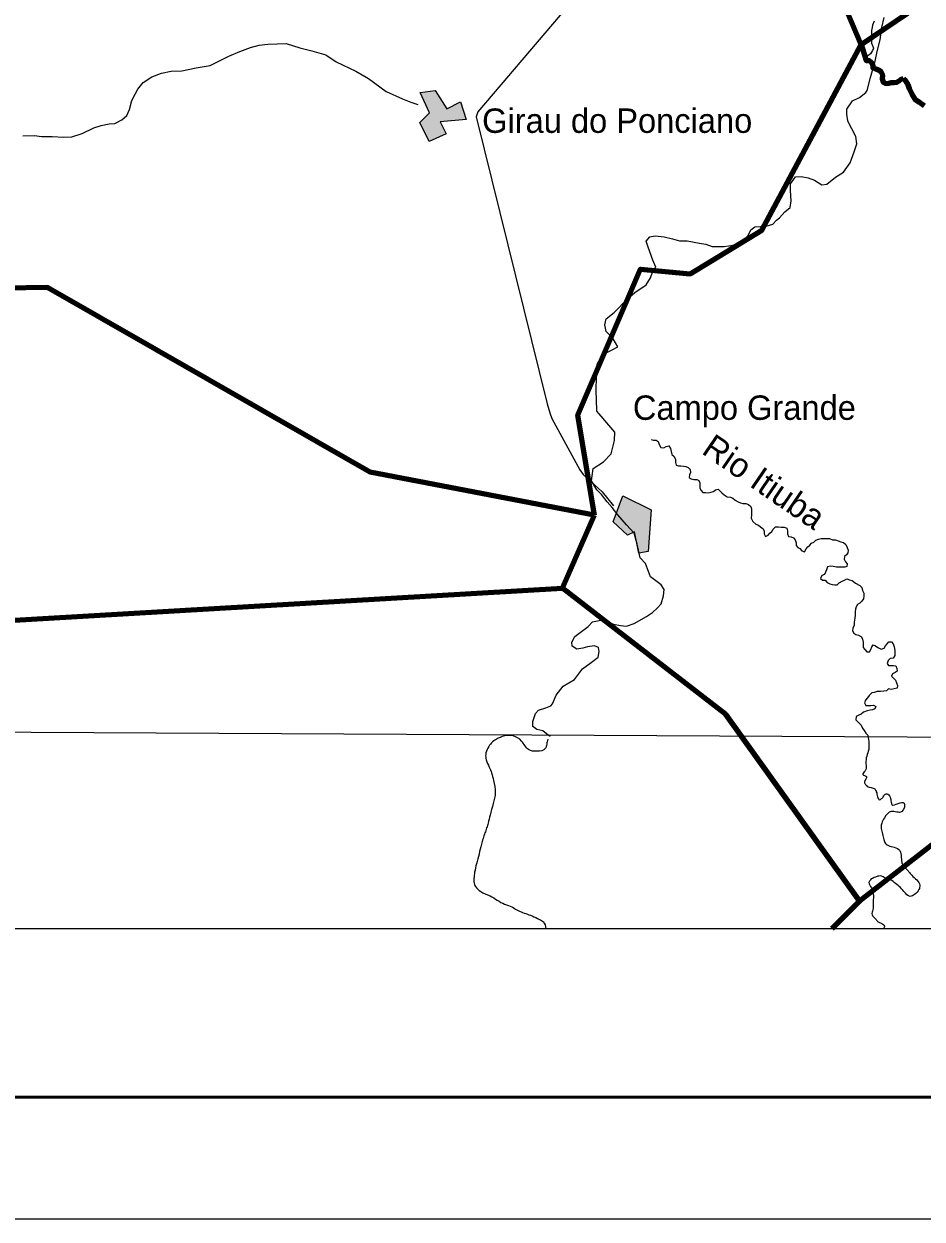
# Model space of a CAD drawing. Extents: x 553962 to 842807, y 8883888 to 9032388.
# Drawn here: x 729677 to 748090, y 8883888 to 8908376 of the extents above; entities that cross this region are included whole.
import ezdxf
from ezdxf.enums import TextEntityAlignment as Align

# ---------------------------------------------------------------- set-up
doc = ezdxf.new("R2010")
doc.units = 0
doc.header["$LTSCALE"] = 200
for name, color, linetype, lineweight in [('1', 7, 'Continuous', 13), ('12', 7, 'Continuous', 25), ('14', 7, 'Continuous', 13), ('21', 7, 'Continuous', 25), ('24', 7, 'Continuous', 25), ('3', 7, 'Continuous', 80), ('9', 7, 'Continuous', 90)]:
    doc.layers.add(name, color=color, linetype=linetype, lineweight=lineweight)
doc.layers.add('41', color=7, linetype='Continuous')
doc.layers.add('49', color=7, linetype='Continuous')

msp = doc.modelspace()

# ---------------------------------------------------------------- hatches: boundary and pattern name
at = {"layer": '21'}
for points in [[(737801.5, 8906970.9), (738106.6, 8907012.5), (738347.6, 8906633.5), (738630.7, 8906778.2), (738745.6, 8906416), (738212.5, 8906368.9), (738331.1, 8906121.9), (737984.3, 8905966.4), (737794.3, 8906356.6), (737990.6, 8906555.2)], [(741953.3, 8898708.5), (742539, 8898421), (742473.5, 8897565.2), (742282.6, 8897532.8), (742195.4, 8897971), (742053.9, 8897898.6), (741759, 8898176.9)]]:
    msp.add_hatch(color=256, dxfattribs=at).paths.add_polyline_path(points)

# ---------------------------------------------------------------- linework, layer by layer
at = {"layer": '1'}
msp.add_lwpolyline([(564751.7, 8894587.5), (664411.9, 8894209.9), (791388.5, 8893536.2)], dxfattribs=at)
at = {"layer": '12'}
for points in [[(746519.8, 8913147), (744583.5, 8912890.8), (744456, 8912865.6), (744221.3, 8912764.1), (744164.9, 8912662.3), (738981.9, 8906574.2), (738945.9, 8906472.4), (740401.6, 8900591.2), (740457, 8900407.7), (740497.3, 8900290.4), (741074.2, 8899240), (741140.1, 8899143.1), (741531, 8898790.9), (741761.4, 8898500.5)], [(732698.6, 8907406), (732912.6, 8907415.8), (733208.3, 8907476.3), (733493.7, 8907526.8), (733646.8, 8907597.8), (733881.6, 8907714.5), (734106.1, 8907810.9), (734320.4, 8907892), (734498.8, 8907937.5), (734677.2, 8907962.7), (734865.7, 8907967.4), (735054.3, 8907977.3), (735334.1, 8907885.1), (735578.4, 8907823.5), (735863.4, 8907741.4), (736076.8, 8907598.4), (736483.7, 8907404.1), (736742.9, 8907255.9), (737103.6, 8906990.3), (737439.3, 8906842), (737612.3, 8906775.4), (737750.2, 8906727.3)], [(729657.5, 8906082), (729896.9, 8906091.7), (730039.5, 8906071.1), (730253.5, 8906065.6), (730497.9, 8906055), (730661, 8906064.9), (730870.1, 8906130.7), (731110, 8906247.4), (731263, 8906293), (731426.1, 8906328.3), (731543.3, 8906338.3), (731686.2, 8906409.4), (731788.5, 8906500.9), (731839.8, 8906623.1), (731891.5, 8906806.3), (731958.2, 8906938.7), (732014.6, 8907040.4), (732122.1, 8907172.7), (732300.8, 8907289.5), (732499.7, 8907365.6), (732698.6, 8907406)]]:
    msp.add_lwpolyline(points, dxfattribs=at)
at = {"layer": '14'}
for points in [[(745102.2, 8904352.2), (745168.7, 8904403), (745276.1, 8904525), (745383.4, 8904616.5), (745404.3, 8904754), (745394.9, 8904962.9), (745395.4, 8905100.4), (745492.7, 8905242.9), (745609.9, 8905247.8), (745752.4, 8905222.1), (745884.7, 8905170.9), (746032.1, 8905078.9), (746139.1, 8905094), (746317.9, 8905236.3), (746481.3, 8905337.9), (746614.5, 8905526.1), (746696.8, 8905755.2), (746753.5, 8905918.1), (746733.6, 8906065.9), (746647.6, 8906229), (746602.1, 8906315.7), (746566.7, 8906392.2), (746546.8, 8906524.7), (746547.2, 8906631.7), (746659.9, 8906799.6), (746807.9, 8906865.5), (746935.6, 8906967.2), (746966.4, 8907012.9), (747033.6, 8907277.7), (747121.3, 8907588.3), (747173.2, 8907837.8), (747230, 8908046.6), (747266.6, 8908301.2), (747313.2, 8908504.9)], [(741412.4, 8901164.9), (741428.6, 8901404.3), (741541.4, 8901602.8), (741720, 8901694.2), (741852.7, 8901760.1), (741756.5, 8901923.3), (741614.4, 8902071.3), (741584.3, 8902208.9), (741610.3, 8902336.2), (741778.9, 8902463.3), (742049.9, 8902742.9), (742198.1, 8902875.1), (742433, 8903027.5), (742520.2, 8903170), (742566.4, 8903287.1), (742633.1, 8903393.9), (742572.5, 8903536.7), (742471.5, 8903801.7), (742436.3, 8903924.1), (742508, 8904010.5), (742615, 8904030.7), (742803.5, 8904015.1), (742976.5, 8903974), (743119, 8903933), (743276.9, 8903932.7), (743526.4, 8903881.3), (743658.8, 8903865.8), (743785.9, 8903814.6), (744035.5, 8903814.1), (744208.8, 8903839.3), (744407.8, 8903920.4), (744525.4, 8904042.5), (744576.8, 8904159.5), (744658.5, 8904215.4), (744892.9, 8904230.3), (745030.6, 8904275.9), (745102.2, 8904352.2)], [(740463, 8893777.9), (740392, 8893831.3), (740315.8, 8893892.6), (740193.7, 8893918.3), (740112.4, 8893979.6), (740107.7, 8894081.4), (740164.3, 8894249.4), (740225.7, 8894315.6), (740378.7, 8894361.1), (740480.7, 8894401.7), (740516.6, 8894447.5), (740588.5, 8894620.5), (740731.8, 8894808.8), (740966.7, 8894940.8), (741130.5, 8895164.6), (741309.3, 8895291.6), (741447.2, 8895398.4), (741468, 8895515.5), (741453.1, 8895602.1), (741371.7, 8895632.8), (741234.1, 8895612.7), (741132.1, 8895587.4), (741009.7, 8895567.3), (740918.2, 8895623.5), (740908.4, 8895710.1), (740969.9, 8895827.1), (741245.8, 8896030.4), (741332.7, 8896127), (741501, 8896162.4), (741587.4, 8896116.4), (741658.7, 8896111.1), (741765.6, 8896075.3), (741908.1, 8896049.6), (742030.3, 8896034.1), (742188.4, 8896089.8), (742438.6, 8896232), (742566.2, 8896313.2), (742668.5, 8896409.8), (742740.1, 8896496.3), (742791.7, 8896659.2), (742802.3, 8896786.6), (742741.6, 8896883.4), (742523.1, 8897046.9), (742417.1, 8897322.1), (742310.6, 8897439.5), (742250.5, 8897714.7), (742190.2, 8897938.9), (742027.8, 8898112.4), (741855.3, 8898316.5), (741733.6, 8898464.5), (741637.2, 8898581.8), (741520.6, 8898734.9), (741424.2, 8898831.8), (741312.8, 8899015.4), (741344.3, 8899265), (741558.7, 8899402.1), (741717.3, 8899569.9), (741784.5, 8899839.8), (741790.2, 8900007.9), (741627.9, 8900201.8), (741470.7, 8900385.4), (741425, 8900441.6), (741415.7, 8900681), (741411.2, 8900849.1), (741412.4, 8901164.9)]]:
    msp.add_lwpolyline(points, dxfattribs=at)
msp.add_spline([(740417.8, 8893718), (740395, 8893617.9), (740366.3, 8893527), (740201.3, 8893471.8), (740024.2, 8893508.9), (739877.2, 8893682.8), (739707.5, 8893786.1), (739358.5, 8893717.2), (739264.2, 8893644.1), (739189.2, 8893539.6), (739143.8, 8893408.5), (739155.2, 8893295.7), (739216.5, 8893150.5), (739263.3, 8893031.3), (739303.8, 8892876.6), (739340.8, 8892619.9), (739297.6, 8892401.9), (739233.3, 8892164.3), (739191.8, 8891997.3), (739163, 8891901.3), (739128.9, 8891800.4), (739054.6, 8891568.2), (739006.8, 8891365.7), (738954.1, 8891168.5), (738917.5, 8890996.2), (738902.9, 8890869.1), (738913.8, 8890741), (738932.9, 8890704.5), (739041.4, 8890598.4), (739232.1, 8890509.7), (739532.1, 8890340.4), (739683, 8890283.8), (739782.9, 8890223.9), (739838, 8890196.4), (740094.7, 8890100.1), (740245.1, 8890028.2), (740325, 8889979.3), (740376.2, 8889839.6), (740376.7, 8889836.8)], degree=3, dxfattribs=at)
at = {"layer": '21'}
for points in [[(737801.5, 8906970.9), (738106.6, 8907012.5), (738347.6, 8906633.5), (738630.7, 8906778.2), (738745.6, 8906416), (738212.5, 8906368.9), (738331.1, 8906121.9), (737984.3, 8905966.4), (737794.3, 8906356.6), (737990.6, 8906555.2)], [(741953.3, 8898708.5), (742539, 8898421), (742473.5, 8897565.2), (742282.6, 8897532.8), (742195.4, 8897971), (742053.9, 8897898.6), (741759, 8898176.9)]]:
    msp.add_lwpolyline(points, close=True, dxfattribs=at)
at = {"layer": '24'}
for points in [[(747110.1, 8908431.2), (747073.9, 8908350), (747068.5, 8908299.1), (747052.8, 8908238.1), (747052.4, 8908177), (747051.8, 8908095.5), (747051.4, 8908034.4), (747051, 8907983.5), (747076.1, 8907932.4), (747091, 8907881.4), (747075.4, 8907830.6), (747029.2, 8907764.6), (746947.3, 8907698.9), (746906.4, 8907668.6), (746941.8, 8907627.7), (747002.8, 8907627.3), (747048.3, 8907591.4), (747078.4, 8907530.1), (747083.1, 8907479.1), (747133.8, 8907458.4), (747194.7, 8907432.6), (747245.3, 8907401.8), (747275.4, 8907335.4), (747274.8, 8907248.8), (747294.7, 8907182.5), (747345.4, 8907156.7), (747406.4, 8907161.4), (747457.4, 8907176.4), (747513.3, 8907176), (747569.3, 8907180.8), (747620.4, 8907211), (747661.3, 8907241.3), (747707.2, 8907261.4)], [(747707.2, 8907261.4), (747727.8, 8907234.4), (747794.5, 8907132.9), (747825.5, 8907051.5), (747877, 8906939.6), (747943.7, 8906833), (748030.5, 8906772.3), (748134.8, 8906696)], [(742537.4, 8899861.4), (742586, 8899849), (742636.8, 8899848.6), (742682.4, 8899822.9), (742702.3, 8899761.6), (742732.4, 8899695.2), (742793.4, 8899689.7), (742844.5, 8899719.9), (742900.5, 8899729.8), (742935.7, 8899678.6), (742945.5, 8899617.4), (742960.3, 8899551.1), (743005.8, 8899510.1), (743035.9, 8899453.8), (743035.5, 8899392.7), (743045.2, 8899331.5), (743096, 8899321), (743146.9, 8899320.7), (743197.7, 8899315.3), (743248.5, 8899304.8), (743294.1, 8899284.1), (743334.5, 8899243.1), (743344.3, 8899187), (743323.6, 8899136.2), (743318.2, 8899085.3), (743358.7, 8899054.4), (743409.4, 8899038.8), (743470.5, 8899038.4), (743516.1, 8899017.8), (743536.1, 8898971.8), (743535.8, 8898920.9), (743535.4, 8898864.8), (743560.5, 8898813.8), (743595.8, 8898777.9), (743646.7, 8898772.4), (743707.7, 8898767), (743763.7, 8898781.9), (743814.7, 8898796.8), (743855.6, 8898827.1), (743906.5, 8898842.1), (743947, 8898811.3), (743982.3, 8898770.3), (744032.9, 8898724.1), (744093.6, 8898683), (744159.7, 8898682.6), (744210.5, 8898661.9), (744261, 8898620.8), (744321.8, 8898584.7), (744367.5, 8898564.1), (744418.2, 8898548.5), (744474.2, 8898548.1), (744530, 8898527.4), (744580.6, 8898491.4), (744595.5, 8898440.3), (744595.1, 8898379.2), (744589.6, 8898318.1), (744584, 8898251.9), (744619.1, 8898180.4), (744679.8, 8898129.1), (744735.6, 8898103.3), (744776.1, 8898072.4), (744831.7, 8898031.3), (744851.8, 8897985.3), (744851.4, 8897929.3), (744881.5, 8897873.1), (744932.6, 8897903.3), (744968.4, 8897938.8), (745009.3, 8897974.2), (745040.2, 8898024.9), (745086.3, 8898070.4), (745147.3, 8898070.1), (745203.2, 8898064.6), (745259.2, 8898064.2), (745315, 8898043.5), (745329.9, 8897992.5), (745329.5, 8897931.3), (745354.5, 8897870.1), (745405.3, 8897869.7), (745456, 8897843.9), (745486.3, 8897803), (745506.2, 8897741.7), (745510.9, 8897690.8), (745541.2, 8897649.8), (745586.8, 8897624.1), (745622.1, 8897583.1), (745677.9, 8897562.4), (745713.9, 8897618.2), (745744.7, 8897663.8), (745785.6, 8897699.2), (745821.5, 8897734.6), (745872.5, 8897759.8), (745913.5, 8897795.2), (745964.5, 8897820.3), (746020.5, 8897835.2), (746076.5, 8897834.9), (746142.6, 8897834.4), (746193.4, 8897829), (746254.3, 8897808.3), (746315.3, 8897807.9), (746371.1, 8897782), (746421.9, 8897766.4)], [(746421.9, 8897766.4), (746477.7, 8897750.8), (746523.2, 8897709.8), (746553.3, 8897648.4), (746573.3, 8897592.3), (746567.8, 8897536.3), (746537, 8897495.7), (746501.2, 8897460.3), (746495.7, 8897409.4), (746520.8, 8897353.2), (746556.1, 8897312.2), (746549.6, 8897261.7), (746504.8, 8897246.3), (746443.7, 8897246.7), (746387.8, 8897247.1), (746336.9, 8897247.4), (746265.8, 8897258.1), (746209.9, 8897263.5), (746148.8, 8897248.6), (746133.1, 8897192.7), (746112.4, 8897141.9), (746091.8, 8897096.2), (746035.7, 8897076.2), (746009.8, 8897015.2), (746050.3, 8896979.3), (746106.2, 8896978.9), (746146.5, 8896927.7), (746197.2, 8896901.9), (746248, 8896891.4), (746298.8, 8896880.9), (746349.7, 8896880.6), (746390.6, 8896921.1), (746451.9, 8896956.3), (746497.9, 8896981.5), (746548.9, 8897006.6), (746599.6, 8896985.9), (746655.5, 8896970.3), (746726.3, 8896918.9), (746812.5, 8896872.5), (746857.9, 8896831.5), (746867.7, 8896770.3), (746892.7, 8896714.1), (746897.4, 8896647.8), (746891.9, 8896596.9), (746856, 8896546.2), (746815.1, 8896510.8), (746764, 8896480.6), (746738.2, 8896434.9), (746722.6, 8896384.1), (746717.2, 8896333.2), (746716.7, 8896261.9), (746711.2, 8896200.8), (746695.4, 8896119.4), (746695, 8896058.2), (746669.1, 8895997.3), (746663.6, 8895941.3), (746688.8, 8895895.3), (746729.2, 8895864.4), (746785.1, 8895853.9), (746845.9, 8895817.9), (746871, 8895771.9), (746880.8, 8895710.7), (746880.3, 8895649.5), (746885.1, 8895598.6), (746915.3, 8895557.6), (746955.7, 8895511.5), (747011.6, 8895511.2), (747037.4, 8895556.8), (747058.1, 8895612.8), (747088.9, 8895653.3), (747134.5, 8895632.6), (747185.2, 8895601.7), (747251.1, 8895565.7), (747312.2, 8895585.7), (747343.1, 8895631.3), (747373.9, 8895676.9), (747404.7, 8895717.5), (747465.7, 8895712), (747495.9, 8895671.1), (747515.9, 8895614.9), (747530.6, 8895538.4), (747530.2, 8895487.5), (747529.9, 8895436.5), (747493.9, 8895380.7), (747432.8, 8895370.9), (747391.9, 8895335.5), (747371.1, 8895274.5), (747401.3, 8895233.6), (747452.2, 8895228.2), (747503, 8895227.8), (747553.9, 8895222.4), (747573.8, 8895166.3), (747578.6, 8895115.3), (747537.7, 8895085), (747481.5, 8895059.9), (747460.9, 8895014.2), (747496.2, 8894978.3), (747541.7, 8894932.2), (747566.7, 8894876), (747586.7, 8894819.8), (747576.1, 8894763.8)], [(747576.1, 8894763.8), (747515, 8894748.9), (747453.9, 8894739.2), (747398, 8894749.7), (747357.1, 8894714.3), (747306.2, 8894704.4), (747234.9, 8894699.8), (747168.8, 8894695.1), (747107.6, 8894675.2), (747056.7, 8894670.4), (747005.5, 8894614.7), (746969.5, 8894569.1), (746928.5, 8894518.4), (746907.8, 8894462.5), (746937.9, 8894411.4), (746988.8, 8894411), (747039.7, 8894410.7), (747095.6, 8894415.4), (747141.2, 8894389.7), (747120.6, 8894344), (747074.7, 8894323.9), (747023.7, 8894314), (746962.6, 8894304.2), (746891.2, 8894274.1), (746840.1, 8894233.7), (746794.2, 8894213.6), (746738, 8894183.4), (746732.5, 8894117.2), (746793.1, 8894055.7), (746838.5, 8894004.5), (746868.6, 8893948.3), (746903.9, 8893897.1), (746934.1, 8893846), (746974.5, 8893805), (746979.5, 8893799.8)]]:
    msp.add_lwpolyline(points, dxfattribs=at)
msp.add_spline([(746979.5, 8893799.8), (746986.5, 8893472.8), (746946.2, 8893341.5), (746940.6, 8893178.3), (746921.6, 8893071.8), (746873.1, 8892996.9), (746953.2, 8892953.1), (746908.6, 8892842.4), (746932.2, 8892790.5), (746966.7, 8892753.5), (747117.8, 8892702), (747151.5, 8892644.6), (747178.3, 8892536.3), (747217.1, 8892478.7), (747258.7, 8892502.7), (747285.1, 8892527.3), (747322.8, 8892587.2), (747384.3, 8892595.2), (747442.4, 8892506.2), (747459.4, 8892408.6), (747468.7, 8892382.7), (747601.9, 8892403.3), (747719.4, 8892409.2), (747672.7, 8892237.3), (747458.7, 8892240.1), (747316.6, 8892112.5), (747261.6, 8891997.1), (747248.6, 8891915.8), (747270.3, 8891807.8), (747301.9, 8891689.2), (747324.6, 8891606.6), (747398.8, 8891542.6), (747519.9, 8891507.5), (747634.7, 8891436.9), (747660.9, 8891308.3), (747729.8, 8891091.3), (747764.6, 8891064.5), (747813.7, 8891011.6), (747877.2, 8890932.7), (748043.5, 8890727.4), (748025.2, 8890641.2), (747934.9, 8890537.3), (747847, 8890499.7), (747718, 8890601.5), (747520.5, 8890787.5), (747410.2, 8890842.6), (747379.7, 8890843.7), (747314.9, 8890886.9), (747203.8, 8890916.5), (747131.6, 8890893.7), (747085.1, 8890874.9), (747079.8, 8890870), (747064.4, 8890865.5), (747033, 8890841.1), (747000.5, 8890786.1), (747052.8, 8890677), (747089.2, 8890553.1), (747088.7, 8890389.7), (747077.9, 8890226.6), (747064.2, 8890125), (747137.8, 8890040.6), (747176.7, 8889988.1), (747236.8, 8889955.3), (747316.1, 8889891.1), (747301, 8889836.8)], degree=3, dxfattribs=at)
at = {"layer": '3', "lineweight": 13}
msp.add_lwpolyline([(842807.3, 9032387.8), (842807.3, 8883887.8), (553961.7, 8883887.8), (553961.7, 9032387.8)], close=True, dxfattribs=at)
at = {"layer": '3', "lineweight": 53}
msp.add_lwpolyline([(840307.3, 9029887.8), (840307.3, 8886387.8), (560211.7, 8886387.8), (560211.7, 9029887.8)], close=True, dxfattribs=at)
at = {"layer": '3', "lineweight": 25}
msp.add_lwpolyline([(563033.9, 9026438.8), (793061.1, 9026438.8), (793495.6, 8889836.8), (563468.3, 8889836.8)], close=True, dxfattribs=at)
at = {"layer": '9'}
for p, q in [((746844.1, 8907956.8), (741055, 8921600.7)), ((746844.1, 8907956.8), (755858.8, 8914075.8)), ((742318.1, 8903350.9), (743333.5, 8903255.5)), ((742318.1, 8903350.9), (743333.5, 8903255.5)), ((741371.9, 8898310.2), (736775.3, 8899194.4)), ((746801.1, 8890392.2), (746237.5, 8889836.8)), ((746801.1, 8890392.2), (746237.5, 8889836.8))]:
    msp.add_line(p, q, dxfattribs=at)
for points in [[(741371.9, 8898310.2), (736775.3, 8899194.4), (730163.4, 8902976.8), (725291.2, 8902898), (725401.2, 8914588.3), (719613.1, 8922670.1)], [(741371.9, 8898310.2), (741034.6, 8900357.7), (742318.1, 8903350.9), (743333.5, 8903255.5), (744802.2, 8904149.6), (746844.1, 8907956.8)], [(746844.1, 8907956.8), (746941.8, 8907627.7), (747002.8, 8907627.3), (747048.3, 8907591.4), (747078.4, 8907530.1), (747083.1, 8907479.1), (747133.8, 8907458.4), (747194.7, 8907432.6), (747245.3, 8907401.8), (747275.4, 8907335.4), (747274.8, 8907248.8), (747294.7, 8907182.5), (747345.4, 8907156.7), (747406.4, 8907161.4), (747457.4, 8907176.4), (747513.3, 8907176), (747569.3, 8907180.8), (747620.4, 8907211), (747661.3, 8907241.3), (747707.2, 8907261.4)], [(746844.1, 8907956.8), (746941.8, 8907627.7), (747002.8, 8907627.3), (747048.3, 8907591.4), (747078.4, 8907530.1), (747083.1, 8907479.1), (747133.8, 8907458.4), (747194.7, 8907432.6), (747245.3, 8907401.8), (747275.4, 8907335.4), (747274.8, 8907248.8), (747294.7, 8907182.5), (747345.4, 8907156.7), (747406.4, 8907161.4), (747457.4, 8907176.4), (747513.3, 8907176), (747569.3, 8907180.8), (747620.4, 8907211), (747661.3, 8907241.3), (747707.2, 8907261.4)], [(747707.2, 8907261.4), (747727.8, 8907234.4), (747794.5, 8907132.9), (747825.5, 8907051.5), (747877, 8906939.6), (747943.7, 8906833), (748030.5, 8906772.3), (748134.8, 8906696)], [(747707.2, 8907261.4), (747727.8, 8907234.4), (747794.5, 8907132.9), (747825.5, 8907051.5), (747877, 8906939.6), (747943.7, 8906833), (748030.5, 8906772.3), (748134.8, 8906696)], [(746808.9, 8890399.8), (752241.5, 8894614.2), (753009.4, 8895516.7), (754051.4, 8895909.3), (754534, 8896055.4), (755222.3, 8896553.7), (755686.3, 8897459.8), (755895.2, 8898166.4), (755953.2, 8899001.4), (756092.4, 8900844.6)], [(746808.9, 8890399.8), (752241.5, 8894614.2), (753009.4, 8895516.7), (754051.4, 8895909.3), (754534, 8896055.4), (755222.3, 8896553.7), (755686.3, 8897459.8), (755895.2, 8898166.4), (755953.2, 8899001.4), (756092.4, 8900844.6)], [(724638.9, 8891123.6), (729122.2, 8896139.1), (740717.5, 8896813.6), (741371.9, 8898310.2)], [(740717.5, 8896813.6), (744056.4, 8894231.8), (746808.9, 8890399.8), (746801.2, 8890392.2)], [(740717.5, 8896813.6), (744056.4, 8894231.8), (746808.9, 8890399.8), (746801.2, 8890392.2)]]:
    msp.add_lwpolyline(points, dxfattribs=at)

# ---------------------------------------------------------------- texts
at = {"layer": '41'}
for s, p in [('Girau do Ponciano', (739070.3, 8906143.2)), ('Campo Grande', (742160.9, 8900263.3))]:
    msp.add_text(s, height=500, dxfattribs=at).set_placement(p)
at = {"layer": '49'}
msp.add_text('Rio Itiuba', height=500, rotation=325.606, dxfattribs=at).set_placement((744712.7, 8898789.2), align=Align.CENTER)

doc.saveas('drawing.dxf')
